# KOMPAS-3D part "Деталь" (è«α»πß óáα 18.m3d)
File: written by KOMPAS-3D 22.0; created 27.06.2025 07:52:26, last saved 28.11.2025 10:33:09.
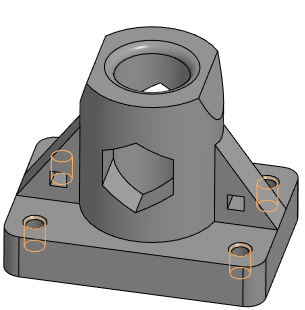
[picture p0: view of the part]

Document properties: Автор: alymovy@yandex.ru; Организация: HP; Полное имя файла: Корпус вар 18.cdw

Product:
- Body: Тело 1
    Материал: Полипропилен ГОСТ 26996-86 (density 900 kg/m3)
    Масса: 0.487897
- Part/product: Деталь
    Материал: Полипропилен ГОСТ 26996-86 (density 900 kg/m3)
    Масса: 0.488581
    Форматы листов документа: A3

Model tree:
1. Эскиз:1
2. Элемент выдавливания:1
     Расстояние 1 = 25
3. Эскиз:2  (with: Элемент выдавливания:1)
4. Элемент выдавливания:2
     Расстояние 1 = 85
5. Скругление:1  (with: Элемент выдавливания:1)
     Радиус = 10
6. Эскиз:3  (with: Скругление:1, Элемент выдавливания:2, Элемент выдавливания:1)
7. Ребро жесткости:1
     Толщина стенки 1 = 20; Толщина стенки 2 = 1
8. Зеркальный массив:1
9. Экземпляр ( 1 )
10. Экземпляр ( 2 )  (with: Ребро жесткости:1)
11. Эскиз:4  (with: Элемент выдавливания:2)
12. Элемент выдавливания:3
     Расстояние 1 = 47.5
13. Эскиз:5  (with: Элемент выдавливания:2)
14. Элемент выдавливания:4
     Расстояние 2 = 110
15. Скругление:2  (with: Элемент выдавливания:4)
     Радиус = 5
16. Эскиз:6  (with: Элемент выдавливания:1)
17. Элемент выдавливания:5  (with: Элемент выдавливания:4)
     Расстояние 1 = 20; Расстояние 2 = 20
18. Эскиз:7  (with: Элемент выдавливания:1)
19. Элемент выдавливания:6
     Расстояние 1 = 47.5
20. Эскиз:8  (with: Элемент выдавливания:1, Элемент выдавливания:2)
21. Отверстие:1  (with: Элемент выдавливания:1, Ребро жесткости:1)  (labels: M11)
     Глубина выреза = 20; Диаметр отверстия = 9.3762; Угол конуса дна = 118; Расстояние 1 = -22; Расстояние 2 = 15; Диаметр зенковки = 12.5762; Глубина зенковки = 1.6; Угол зенковки = 90
22. M11  (labels: cil0_24705-2004 coarse)
     Длина резьбы = 15; Шаг резьбы = 1.5; Номинальный диаметр резьбы = 11
23. Зеркальный массив:2  (with: Экземпляр ( 1 ), Экземпляр ( 2 ), Отверстие:1)
24. Зеркальный массив:3  (with: Экземпляр ( 1 ), Экземпляр ( 2 ), Зеркальный массив:2, Отверстие:1)
25. Экземпляр ( 2 )  (with: Отверстие:1)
